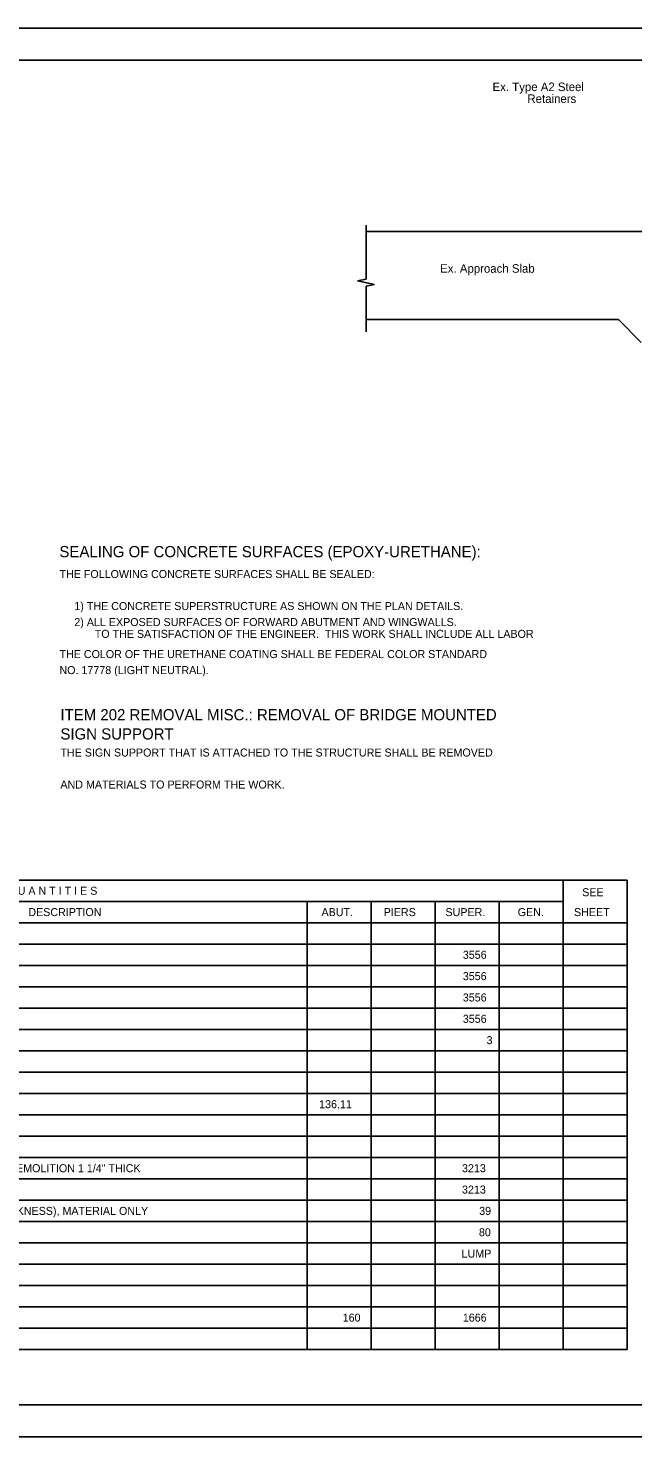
# Model space of a CAD drawing. Extents: x -706 to 14950, y -1867 to 6417.
# Drawn here: x 171 to 454, y -1737 to -1077 of the extents above; entities that cross this region are included whole.
import ezdxf

# ---------------------------------------------------------------- set-up
doc = ezdxf.new("R2010")
doc.units = 0
for name, color, linetype in [('Level 1', 7, 'Continuous'), ('Level 41', 7, 'Continuous'), ('Level 42', 7, 'Continuous'), ('Level 44', 7, 'Continuous')]:
    doc.layers.add(name, color=color, linetype=linetype)

msp = doc.modelspace()

# ---------------------------------------------------------------- linework, layer by layer
at = {"layer": 'Level 1'}
for points in [[(-211.83, -1076.66), (808.17, -1076.66), (808.17, -1736.66), (-211.83, -1736.66)], [(-151.83, -1091.66), (793.17, -1091.66), (793.17, -1721.66), (-151.83, -1721.66)]]:
    msp.add_lwpolyline(points, close=True, dxfattribs=at)
at = {"layer": 'Level 42'}
for p, q in [((329.12, -1171.85), (486.08, -1171.85)), ((447.27, -1213.22), (329.12, -1213.22)), ((457.95, -1223.91), (447.27, -1213.22)), ((-132.93, -1475.81), (451.45, -1475.81)), ((421.45, -1475.81), (421.45, -1485.81)), ((451.45, -1475.81), (451.45, -1695.81)), ((-132.93, -1485.81), (421.45, -1485.81)), ((301.45, -1485.81), (301.45, -1495.81)), ((331.45, -1485.81), (331.45, -1495.81)), ((361.45, -1485.81), (361.45, -1495.81)), ((391.45, -1485.81), (391.45, -1495.81)), ((421.45, -1485.81), (421.45, -1495.81)), ((-132.93, -1495.81), (451.45, -1495.81)), ((-132.93, -1495.81), (421.45, -1495.81)), ((301.45, -1495.81), (301.45, -1505.81)), ((331.45, -1495.81), (331.45, -1505.81)), ((361.45, -1495.81), (361.45, -1505.81)), ((391.45, -1495.81), (391.45, -1505.81)), ((421.45, -1495.81), (421.45, -1505.81)), ((-132.93, -1505.81), (451.45, -1505.81)), ((301.45, -1505.81), (301.45, -1515.81)), ((331.45, -1505.81), (331.45, -1515.81)), ((361.45, -1505.81), (361.45, -1515.81)), ((391.45, -1505.81), (391.45, -1515.81)), ((421.45, -1505.81), (421.45, -1515.81)), ((-132.93, -1515.81), (451.45, -1515.81)), ((301.45, -1515.81), (301.45, -1525.81)), ((331.45, -1515.81), (331.45, -1525.81)), ((361.45, -1515.81), (361.45, -1525.81)), ((391.45, -1515.81), (391.45, -1525.81)), ((421.45, -1515.81), (421.45, -1525.81)), ((-132.93, -1525.81), (451.45, -1525.81)), ((301.45, -1525.81), (301.45, -1535.81)), ((331.45, -1525.81), (331.45, -1535.81)), ((361.45, -1525.81), (361.45, -1535.81)), ((391.45, -1525.81), (391.45, -1535.81)), ((421.45, -1525.81), (421.45, -1535.81)), ((-132.93, -1535.81), (451.45, -1535.81)), ((301.45, -1535.81), (301.45, -1545.81)), ((301.45, -1535.81), (301.45, -1545.81)), ((331.45, -1535.81), (331.45, -1545.81)), ((331.45, -1535.81), (331.45, -1545.81)), ((361.45, -1535.81), (361.45, -1545.81)), ((361.45, -1535.81), (361.45, -1545.81)), ((391.45, -1535.81), (391.45, -1545.81)), ((391.45, -1535.81), (391.45, -1545.81)), ((421.45, -1535.81), (421.45, -1545.81)), ((-132.93, -1545.81), (451.45, -1545.81)), ((301.45, -1545.81), (301.45, -1555.81)), ((301.45, -1545.81), (301.45, -1555.81)), ((331.45, -1545.81), (331.45, -1555.81)), ((331.45, -1545.81), (331.45, -1555.81)), ((361.45, -1545.81), (361.45, -1555.81)), ((361.45, -1545.81), (361.45, -1555.81)), ((391.45, -1545.81), (391.45, -1555.81)), ((391.45, -1545.81), (391.45, -1555.81)), ((421.45, -1545.81), (421.45, -1555.81)), ((-132.93, -1555.81), (451.45, -1555.81)), ((301.45, -1555.81), (301.45, -1565.81)), ((301.45, -1555.81), (301.45, -1565.81)), ((331.45, -1555.81), (331.45, -1565.81)), ((331.45, -1555.81), (331.45, -1565.81)), ((361.45, -1555.81), (361.45, -1565.81)), ((361.45, -1555.81), (361.45, -1565.81)), ((391.45, -1555.81), (391.45, -1565.81)), ((391.45, -1555.81), (391.45, -1565.81)), ((421.45, -1555.81), (421.45, -1565.81)), ((-132.93, -1565.81), (451.45, -1565.81)), ((301.45, -1565.81), (301.45, -1575.81)), ((301.45, -1565.81), (301.45, -1575.81)), ((331.45, -1565.81), (331.45, -1575.81)), ((331.45, -1565.81), (331.45, -1575.81)), ((361.45, -1565.81), (361.45, -1575.81)), ((361.45, -1565.81), (361.45, -1575.81)), ((391.45, -1565.81), (391.45, -1575.81)), ((391.45, -1565.81), (391.45, -1575.81)), ((421.45, -1565.81), (421.45, -1575.81)), ((-132.93, -1575.81), (451.45, -1575.81)), ((301.45, -1575.81), (301.45, -1585.81)), ((301.45, -1575.81), (301.45, -1585.81)), ((331.45, -1575.81), (331.45, -1585.81)), ((331.45, -1575.81), (331.45, -1585.81)), ((361.45, -1575.81), (361.45, -1585.81)), ((361.45, -1575.81), (361.45, -1585.81)), ((391.45, -1575.81), (391.45, -1585.81)), ((391.45, -1575.81), (391.45, -1585.81)), ((421.45, -1575.81), (421.45, -1585.81)), ((-132.93, -1585.81), (451.45, -1585.81)), ((301.45, -1585.81), (301.45, -1595.81)), ((301.45, -1585.81), (301.45, -1595.81)), ((331.45, -1585.81), (331.45, -1595.81)), ((331.45, -1585.81), (331.45, -1595.81)), ((361.45, -1585.81), (361.45, -1595.81)), ((361.45, -1585.81), (361.45, -1595.81)), ((391.45, -1585.81), (391.45, -1595.81)), ((391.45, -1585.81), (391.45, -1595.81)), ((421.45, -1585.81), (421.45, -1595.81)), ((-132.93, -1595.81), (451.45, -1595.81)), ((301.45, -1595.81), (301.45, -1605.81)), ((331.45, -1595.81), (331.45, -1605.81)), ((361.45, -1595.81), (361.45, -1605.81)), ((391.45, -1595.81), (391.45, -1605.81)), ((421.45, -1595.81), (421.45, -1605.81)), ((-132.93, -1605.81), (451.45, -1605.81)), ((301.45, -1605.81), (301.45, -1615.81)), ((331.45, -1605.81), (331.45, -1615.81)), ((361.45, -1605.81), (361.45, -1615.81)), ((391.45, -1605.81), (391.45, -1615.81)), ((421.45, -1605.81), (421.45, -1615.81)), ((-132.93, -1615.81), (451.45, -1615.81)), ((301.45, -1615.81), (301.45, -1625.81)), ((331.45, -1615.81), (331.45, -1625.81)), ((361.45, -1615.81), (361.45, -1625.81)), ((391.45, -1615.81), (391.45, -1625.81)), ((421.45, -1615.81), (421.45, -1625.81)), ((-132.93, -1625.81), (451.45, -1625.81)), ((301.45, -1625.81), (301.45, -1635.81)), ((331.45, -1625.81), (331.45, -1635.81)), ((361.45, -1625.81), (361.45, -1635.81)), ((391.45, -1625.81), (391.45, -1635.81)), ((421.45, -1625.81), (421.45, -1635.81)), ((-132.93, -1635.81), (451.45, -1635.81)), ((301.45, -1635.81), (301.45, -1645.81)), ((331.45, -1635.81), (331.45, -1645.81)), ((361.45, -1635.81), (361.45, -1645.81)), ((391.45, -1635.81), (391.45, -1645.81)), ((421.45, -1635.81), (421.45, -1645.81)), ((-132.93, -1645.81), (451.45, -1645.81)), ((301.45, -1645.81), (301.45, -1655.81)), ((331.45, -1645.81), (331.45, -1655.81)), ((361.45, -1645.81), (361.45, -1655.81)), ((391.45, -1645.81), (391.45, -1655.81)), ((421.45, -1645.81), (421.45, -1655.81)), ((-132.93, -1655.81), (451.45, -1655.81)), ((301.45, -1655.81), (301.45, -1665.81)), ((331.45, -1655.81), (331.45, -1665.81)), ((361.45, -1655.81), (361.45, -1665.81)), ((391.45, -1655.81), (391.45, -1665.81)), ((421.45, -1655.81), (421.45, -1665.81)), ((-132.93, -1665.81), (451.45, -1665.81)), ((301.45, -1665.81), (301.45, -1675.81)), ((331.45, -1665.81), (331.45, -1675.81)), ((361.45, -1665.81), (361.45, -1675.81)), ((391.45, -1665.81), (391.45, -1675.81)), ((421.45, -1665.81), (421.45, -1675.81)), ((-132.93, -1675.81), (451.45, -1675.81)), ((301.45, -1675.81), (301.45, -1685.81)), ((331.45, -1675.81), (331.45, -1685.81)), ((361.45, -1675.81), (361.45, -1685.81)), ((391.45, -1675.81), (391.45, -1685.81)), ((421.45, -1675.81), (421.45, -1685.81)), ((-132.93, -1685.81), (451.45, -1685.81)), ((301.45, -1685.81), (301.45, -1695.81)), ((331.45, -1685.81), (331.45, -1695.81)), ((361.45, -1685.81), (361.45, -1695.81)), ((391.45, -1685.81), (391.45, -1695.81)), ((421.45, -1685.81), (421.45, -1695.81)), ((-132.93, -1695.81), (451.45, -1695.81))]:
    msp.add_line(p, q, dxfattribs=at)
at = {"layer": 'Level 44'}
for p, q in [((329.12, -1168.93), (329.12, -1194.29)), ((325.06, -1194.99), (329.12, -1194.29)), ((332.96, -1196.81), (325.06, -1194.99)), ((329.12, -1197.46), (332.96, -1196.81)), ((329.12, -1197.46), (329.12, -1218.87))]:
    msp.add_line(p, q, dxfattribs=at)

# ---------------------------------------------------------------- texts
at = {"layer": 'Level 41'}
for s, height, p in [('SEALING OF CONCRETE SURFACES (EPOXY-URETHANE):', 5.25, (185.41, -1324.54)), ('THE FOLLOWING CONCRETE SURFACES SHALL BE SEALED:', 3.75, (185.41, -1334.29)), ('     1) THE CONCRETE SUPERSTRUCTURE AS SHOWN ON THE PLAN DETAILS.', 3.75, (185.41, -1349.29)), ('     2) ALL EXPOSED SURFACES OF FORWARD ABUTMENT AND WINGWALLS.', 3.75, (185.41, -1356.79)), ('TO THE SATISFACTION OF THE ENGINEER.  THIS WORK SHALL INCLUDE ALL LABOR ', 3.75, (201.94, -1362.31)), ('THE COLOR OF THE URETHANE COATING SHALL BE FEDERAL COLOR STANDARD', 3.75, (185.41, -1371.79)), ('NO. 17778 (LIGHT NEUTRAL).', 3.75, (185.41, -1379.29)), ('ITEM 202 REMOVAL MISC.: REMOVAL OF BRIDGE MOUNTED ', 5.25, (185.86, -1400.95)), ('SIGN SUPPORT', 5.25, (185.86, -1409.95)), ('THE SIGN SUPPORT THAT IS ATTACHED TO THE STRUCTURE SHALL BE REMOVED ', 3.75, (185.86, -1417.91)), ('AND MATERIALS TO PERFORM THE WORK.', 3.75, (185.86, -1432.91))]:
    msp.add_text(s, height=height, dxfattribs=at).set_placement(p)
at = {"layer": 'Level 44'}
for s, height, p in [('Ex. Type A2 Steel', 4, (388.32, -1106.14)), ('Retainers', 4, (404.65, -1111.7)), ('Ex. Approach Slab', 4, (363.77, -1191.25)), ('E S T I M A T E D    Q U A N T I T I E S', 3.75, (115.13, -1482.68)), ('SEE', 3.75, (430.33, -1483.36)), ('DESCRIPTION', 3.75, (170.83, -1492.68)), ('ABUT.', 3.75, (308.18, -1492.68)), ('PIERS', 3.75, (337.31, -1492.68)), ('SUPER.', 3.75, (366.26, -1492.68)), ('GEN.', 3.75, (400.1, -1492.68)), ('SHEET', 3.75, (426.48, -1492.68)), ('3556', 3.75, (374.39, -1512.68)), ('3556', 3.75, (374.39, -1522.68)), ('3556', 3.75, (374.39, -1532.68)), ('3556', 3.75, (374.39, -1542.68)), ('3', 3.75, (385.52, -1552.68)), ('136.11', 3.75, (307.07, -1582.68)), ('MICRO SILICA MODIFIED CONCRETE OVERLAY USING HYDRODEMOLITION 1 1/4" THICK', 3.75, (10.17, -1612.68)), ('3213', 3.75, (374.01, -1612.68)), ('3213', 3.75, (374.01, -1622.68)), ('MICRO SILICA MODIFIED CONCRETE OVERLAY (VARIABLE THICKNESS), MATERIAL ONLY', 3.75, (10.17, -1632.68)), ('39', 3.75, (382.07, -1632.68)), ('80', 3.75, (381.95, -1642.68)), ('LUMP', 3.75, (373.83, -1652.68)), ('160', 3.75, (318.11, -1682.68)), ('1666', 3.75, (374.39, -1682.68))]:
    msp.add_text(s, height=height, dxfattribs=at).set_placement(p)

doc.saveas('drawing.dxf')
